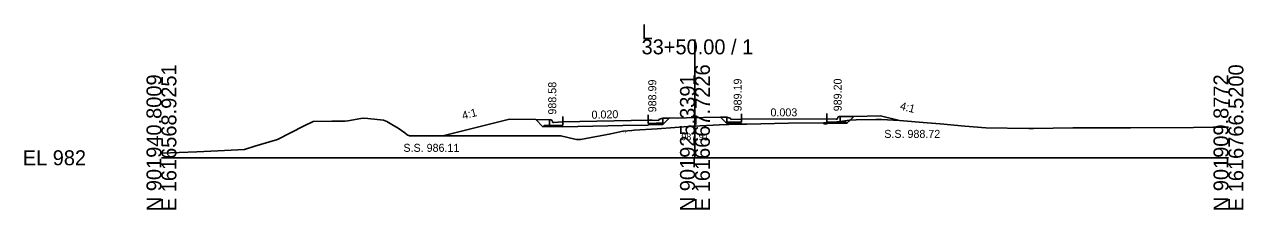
# Model space of a CAD drawing. Extents: x 1009 to 7438, y -1586 to 7964.
# Drawn here: x 3009.2 to 3237.7, y 1414 to 1448.7 of the extents above; entities that cross this region are included whole.
import ezdxf

# ---------------------------------------------------------------- set-up
doc = ezdxf.new("R2010")
doc.units = 0
for name, color, linetype in [('Exist Cross Section Cell', 7, 'Continuous'), ('Exist XS Center Line Elevation Label', 7, 'Continuous'), ('Exist XS Ground Line', 7, 'Continuous'), ('Prop XS Dump Level', 7, 'Continuous'), ('Prop XS Earthwork Shape', 7, 'Continuous'), ('Prop XS EOT Tick Mark', 7, 'Continuous'), ('Prop XS Finish Grade', 7, 'Continuous'), ('Prop XS Finish Grade CurbGutter', 7, 'Continuous'), ('Prop XS Finish Grade Earthwork', 7, 'Continuous'), ('Prop XS Finish Grade Pavement', 7, 'Continuous'), ('Prop XS Hydro Elevations', 7, 'Continuous'), ('Prop XS Pvmt Edge Slope', 7, 'Continuous'), ('Prop XS SE Text', 7, 'Continuous'), ('Prop XS Side Slope Text', 7, 'Continuous'), ('Prop XS SS Elevation Text', 7, 'Continuous'), ('Prop XS Subgrade CurbGutter', 7, 'Continuous'), ('Prop XS Subgrade Earthwork', 7, 'Continuous')]:
    doc.layers.add(name, color=color, linetype=linetype)

msp = doc.modelspace()

# ---------------------------------------------------------------- linework, layer by layer
at = {"layer": 'Exist Cross Section Cell'}
for p, q in [((3134.89, 1423.73), (3134.89, 1445.89)), ((3034.89, 1423.73), (3134.89, 1423.73)), ((3134.89, 1423.73), (3234.89, 1423.73))]:
    msp.add_line(p, q, dxfattribs=at)
at = {"layer": 'Exist XS Ground Line'}
for p, q in [((3069.29, 1430.61), (3069.82, 1430.64)), ((3069.82, 1430.64), (3072.26, 1431.1)), ((3072.26, 1431.1), (3072.81, 1431.12)), ((3072.81, 1431.12), (3073.56, 1431.08)), ((3073.56, 1431.08), (3076.52, 1430.78)), ((3076.52, 1430.78), (3077.14, 1430.51)), ((3162.09, 1430.52), (3163.84, 1430.77)), ((3163.84, 1430.77), (3165.1, 1430.82)), ((3165.1, 1430.82), (3168.78, 1430.89)), ((3168.78, 1430.89), (3169.86, 1430.89)), ((3169.86, 1430.89), (3173.25, 1430.69)), ((3173.25, 1430.69), (3178.43, 1430.29)), ((3056.63, 1427.17), (3061.67, 1429.69)), ((3061.67, 1429.69), (3063.31, 1430.51)), ((3063.31, 1430.51), (3066.84, 1430.57)), ((3066.84, 1430.57), (3067.58, 1430.58)), ((3067.58, 1430.58), (3069.29, 1430.61)), ((3077.14, 1430.51), (3078.07, 1429.96)), ((3078.07, 1429.96), (3079.25, 1429.26)), ((3079.25, 1429.26), (3080.53, 1428.38)), ((3080.53, 1428.38), (3080.96, 1428.03)), ((3119.1, 1428.22), (3121.39, 1428.7)), ((3121.39, 1428.7), (3123.05, 1428.85)), ((3123.05, 1428.85), (3123.52, 1428.88)), ((3123.52, 1428.88), (3127.81, 1429.17)), ((3127.81, 1429.17), (3134.41, 1429.62)), ((3134.41, 1429.62), (3134.89, 1429.64)), ((3134.89, 1429.64), (3135.86, 1429.7)), ((3135.86, 1429.7), (3139.49, 1429.91)), ((3139.49, 1429.91), (3143, 1430.01)), ((3143, 1430.01), (3144.59, 1430.04)), ((3144.59, 1430.04), (3152.41, 1430.18)), ((3152.41, 1430.18), (3159.05, 1430.29)), ((3159.05, 1430.29), (3160.07, 1430.32)), ((3160.07, 1430.32), (3160.84, 1430.33)), ((3160.84, 1430.33), (3162.09, 1430.52)), ((3178.43, 1430.29), (3180.88, 1430.06)), ((3180.88, 1430.06), (3185.5, 1429.66)), ((3185.5, 1429.66), (3189.41, 1429.33)), ((3189.41, 1429.33), (3197.45, 1429.24)), ((3197.45, 1429.24), (3197.92, 1429.24)), ((3197.92, 1429.24), (3198.35, 1429.24)), ((3198.35, 1429.24), (3205.72, 1429.31)), ((3205.72, 1429.31), (3206.09, 1429.32)), ((3206.09, 1429.32), (3213.46, 1429.35)), ((3213.46, 1429.35), (3215.01, 1429.34)), ((3215.01, 1429.34), (3216.54, 1429.34)), ((3216.54, 1429.34), (3228.31, 1429.4)), ((3228.31, 1429.4), (3232.05, 1429.46)), ((3232.05, 1429.46), (3234.89, 1429.49)), ((3052.39, 1425.88), (3056.63, 1427.17)), ((3080.96, 1428.03), (3081.37, 1427.83)), ((3081.37, 1427.83), (3091.26, 1427.84)), ((3091.26, 1427.84), (3100.82, 1427.85)), ((3100.82, 1427.85), (3101.17, 1427.85)), ((3101.17, 1427.85), (3105.63, 1427.85)), ((3105.63, 1427.85), (3108.5, 1427.84)), ((3108.5, 1427.84), (3109.74, 1427.84)), ((3109.74, 1427.84), (3112.4, 1427.19)), ((3112.4, 1427.19), (3112.71, 1427.12)), ((3112.71, 1427.12), (3113.46, 1427.12)), ((3113.46, 1427.12), (3119.1, 1428.22)), ((3034.89, 1424.61), (3041.52, 1424.84)), ((3041.52, 1424.84), (3045.45, 1425.03)), ((3045.45, 1425.03), (3050.48, 1425.27)), ((3050.48, 1425.27), (3052.39, 1425.88))]:
    msp.add_line(p, q, dxfattribs=at)
at = {"layer": 'Prop XS Dump Level'}
for p, q in [((3110.14, 1430.43), (3126.14, 1430.75)), ((3110.14, 1430.43), (3126.14, 1430.75)), ((3143.64, 1430.95), (3159.64, 1431)), ((3143.64, 1430.95), (3159.64, 1431))]:
    msp.add_line(p, q, dxfattribs=at)
at = {"layer": 'Prop XS Earthwork Shape'}
for points in [[(3128.89, 1429.98), (3130.07, 1431.16), (3130.12, 1431.16), (3139.65, 1431.36), (3140.89, 1430.12), (3143.64, 1430.12), (3143.64, 1430.04), (3143.64, 1430.02), (3143, 1430.01), (3139.49, 1429.91), (3135.86, 1429.7), (3134.89, 1429.64), (3134.41, 1429.62), (3127.81, 1429.17), (3123.52, 1428.88), (3123.05, 1428.85), (3121.39, 1428.7), (3119.1, 1428.22), (3113.46, 1427.12), (3112.71, 1427.12), (3112.4, 1427.19), (3109.74, 1427.84), (3108.5, 1427.84), (3105.63, 1427.85), (3101.17, 1427.85), (3100.82, 1427.85), (3091.26, 1427.84), (3087.62, 1427.84), (3100.14, 1430.97), (3105.05, 1430.87), (3106.39, 1429.53), (3110.14, 1429.6), (3110.14, 1429.52), (3121.39, 1429.74), (3126.14, 1429.84), (3126.14, 1429.92)], [(3163.39, 1430.19), (3163.98, 1430.77), (3163.84, 1430.77), (3162.14, 1430.53), (3162.14, 1430.43), (3163.14, 1430.43)], [(3163.98, 1430.77), (3165.1, 1430.82), (3168.78, 1430.89), (3169.86, 1430.89), (3173.22, 1430.69), (3169.64, 1431.59), (3164.69, 1431.48)], [(3161.48, 1430.43), (3162.14, 1430.43), (3163.14, 1430.43), (3163.39, 1430.19), (3159.64, 1430.17), (3159.64, 1430.09), (3159.05, 1430.09), (3159.05, 1430.29), (3160.07, 1430.32), (3160.84, 1430.33)], [(3161.48, 1430.43), (3162.14, 1430.43), (3162.14, 1430.53), (3162.09, 1430.52)]]:
    msp.add_lwpolyline(points, close=True, dxfattribs=at)
at = {"layer": 'Prop XS EOT Tick Mark'}
for p, q in [((3110.14, 1430.43), (3110.14, 1431.43)), ((3126.14, 1430.75), (3126.14, 1431.75)), ((3143.64, 1430.95), (3143.64, 1431.95)), ((3159.64, 1431), (3159.64, 1432))]:
    msp.add_line(p, q, dxfattribs=at)
at = {"layer": 'Prop XS Finish Grade'}
for p, q in [((3107.64, 1430.81), (3105.05, 1430.87)), ((3128.89, 1431.13), (3130.12, 1431.16)), ((3140.89, 1431.33), (3139.65, 1431.36)), ((3162.14, 1431.43), (3164.69, 1431.48))]:
    msp.add_line(p, q, dxfattribs=at)
at = {"layer": 'Prop XS Finish Grade CurbGutter'}
for p, q in [((3107.64, 1430.81), (3107.89, 1430.81)), ((3107.89, 1430.81), (3108.02, 1430.78)), ((3108.11, 1430.69), (3108.02, 1430.78)), ((3108.18, 1430.44), (3108.11, 1430.69)), ((3126.14, 1430.75), (3126.89, 1430.74)), ((3126.14, 1430.75), (3128.14, 1430.71)), ((3128.14, 1430.88), (3128.89, 1431.13)), ((3128.14, 1430.71), (3128.14, 1430.88)), ((3141.64, 1431.08), (3140.89, 1431.33)), ((3141.64, 1430.91), (3141.64, 1431.08)), ((3143.64, 1430.95), (3141.64, 1430.91)), ((3159.64, 1431), (3161.39, 1430.94)), ((3161.39, 1430.94), (3161.52, 1430.96)), ((3161.52, 1430.96), (3161.61, 1431.05)), ((3161.61, 1431.05), (3161.68, 1431.3)), ((3161.68, 1431.3), (3161.77, 1431.4)), ((3161.89, 1431.43), (3161.77, 1431.4)), ((3162.14, 1431.43), (3161.89, 1431.43)), ((3108.27, 1430.35), (3108.18, 1430.44)), ((3108.39, 1430.33), (3108.27, 1430.35)), ((3110.14, 1430.43), (3108.39, 1430.33))]:
    msp.add_line(p, q, dxfattribs=at)
at = {"layer": 'Prop XS Finish Grade Earthwork'}
for p, q in [((3100.14, 1430.97), (3087.62, 1427.84)), ((3105.05, 1430.87), (3100.14, 1430.97)), ((3130.12, 1431.16), (3139.65, 1431.36)), ((3164.69, 1431.48), (3169.64, 1431.59)), ((3169.64, 1431.59), (3173.22, 1430.69))]:
    msp.add_line(p, q, dxfattribs=at)
at = {"layer": 'Prop XS Finish Grade Pavement'}
for p, q in [((3110.14, 1430.43), (3126.14, 1430.75)), ((3143.64, 1430.95), (3159.64, 1431))]:
    msp.add_line(p, q, dxfattribs=at)
at = {"layer": 'Prop XS Pvmt Edge Slope'}
for p, q in [((3106.64, 1429.78), (3106.39, 1429.53)), ((3107.64, 1429.8), (3106.64, 1429.78)), ((3127.64, 1430.2), (3128.89, 1430.23)), ((3127.64, 1430.2), (3128.64, 1430.22)), ((3128.64, 1430.22), (3128.89, 1429.98)), ((3141.14, 1430.37), (3140.89, 1430.12)), ((3142.14, 1430.37), (3140.89, 1430.37)), ((3162.14, 1430.43), (3163.14, 1430.43)), ((3163.14, 1430.43), (3163.39, 1430.19))]:
    msp.add_line(p, q, dxfattribs=at)
at = {"layer": 'Prop XS Subgrade CurbGutter'}
for p, q in [((3107.64, 1429.8), (3107.64, 1430.81)), ((3126.14, 1430.75), (3126.14, 1430.17)), ((3128.89, 1430.23), (3128.89, 1431.13)), ((3140.89, 1430.37), (3140.89, 1431.33)), ((3143.64, 1430.95), (3143.64, 1430.37)), ((3159.64, 1431), (3159.64, 1430.42)), ((3162.14, 1430.43), (3162.14, 1431.43)), ((3110.14, 1429.85), (3107.64, 1429.8)), ((3110.14, 1430.43), (3110.14, 1429.85)), ((3126.14, 1430.17), (3127.64, 1430.2)), ((3143.64, 1430.37), (3142.14, 1430.37)), ((3159.64, 1430.42), (3162.14, 1430.43))]:
    msp.add_line(p, q, dxfattribs=at)
at = {"layer": 'Prop XS Subgrade Earthwork'}
for p, q in [((3106.39, 1429.53), (3105.05, 1430.87)), ((3128.89, 1429.98), (3130.07, 1431.16)), ((3140.89, 1430.12), (3139.65, 1431.36)), ((3163.39, 1430.19), (3164.69, 1431.48)), ((3110.14, 1429.6), (3106.39, 1429.53)), ((3121.39, 1429.74), (3110.14, 1429.52)), ((3110.14, 1429.52), (3110.14, 1429.6)), ((3121.39, 1429.74), (3126.14, 1429.84)), ((3126.14, 1429.92), (3128.89, 1429.98)), ((3126.14, 1429.84), (3126.14, 1429.92)), ((3143.64, 1430.12), (3140.89, 1430.12)), ((3143.64, 1430.04), (3143.64, 1430.12)), ((3143.64, 1430.04), (3143.64, 1430.02)), ((3159.05, 1430.09), (3159.05, 1430.29)), ((3159.05, 1430.09), (3159.64, 1430.09)), ((3159.64, 1430.17), (3163.39, 1430.19)), ((3159.64, 1430.09), (3159.64, 1430.17))]:
    msp.add_line(p, q, dxfattribs=at)

# ---------------------------------------------------------------- texts
at = {"layer": 'Exist Cross Section Cell'}
for s, p in [('L', (3124.89, 1445.89)), ('33+50.00 / 1', (3124.89, 1443.09)), ('EL 982', (3008.89, 1422.33))]:
    msp.add_text(s, height=2.8, dxfattribs=at).set_placement(p)
for s, p in [('E 1616568.9251', (3037.69, 1413.73)), ('E 1616667.7226', (3137.69, 1413.73)), ('E 1616766.5200', (3237.69, 1413.73)), ('N 901940.8009', (3034.89, 1413.73)), ('N 901925.3391', (3134.89, 1413.73)), ('N 901909.8772', (3234.89, 1413.73))]:
    msp.add_text(s, height=2.8, rotation=90, dxfattribs=at).set_placement(p)
at = {"layer": 'Exist XS Center Line Elevation Label'}
msp.add_text('987.91', height=1.25, dxfattribs=at).set_placement((3132.34, 1427.02))
at = {"layer": 'Prop XS Dump Level'}
for p in [(3121.39, 1428.4), (3121.39, 1428.4), (3121.39, 1428.4), (3159.05, 1429.99)]:
    msp.add_text('Eop', height=0.3, dxfattribs=at).set_placement(p)
at = {"layer": 'Prop XS Hydro Elevations'}
for s, p in [('988.58', (3108.89, 1431.81)), ('988.99', (3127.64, 1432.24)), ('989.19', (3143.64, 1432.42)), ('989.20', (3162.39, 1432.43))]:
    msp.add_text(s, height=1.5, rotation=90, dxfattribs=at).set_placement(p)
at = {"layer": 'Prop XS SE Text'}
for s, rotation, p in [('0.003', 0.1769, (3149.05, 1431.47)), ('0.020', 1.1458, (3115.52, 1431.04))]:
    msp.add_text(s, height=1.5, rotation=rotation, dxfattribs=at).set_placement(p)
at = {"layer": 'Prop XS Side Slope Text'}
for rotation, p in [(14.0362, (3091.43, 1430.88)), (345.9638, (3173.22, 1432.78))]:
    msp.add_text('4:1', height=1.5, rotation=rotation, dxfattribs=at).set_placement(p)
at = {"layer": 'Prop XS SS Elevation Text'}
for s, p in [('S.S. 988.72', (3170.38, 1427.45)), ('S.S. 986.11', (3080.25, 1424.84))]:
    msp.add_text(s, height=1.5, dxfattribs=at).set_placement(p)

doc.saveas('drawing.dxf')
